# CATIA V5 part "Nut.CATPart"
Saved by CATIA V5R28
Part number: Nut
Bounding box of the stored display mesh (mm): x -6.998 to 6.998, y -6.998 to 6.998, z -4 to 15
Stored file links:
  C:\Users\Parisa\Desktop\tarah sanat\CAR JACK\Nut.CATPart
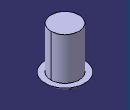
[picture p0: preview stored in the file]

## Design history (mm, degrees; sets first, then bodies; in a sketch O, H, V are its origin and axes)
Body1 (main body)
  Sketch1 on xy-plane, origin (0, 0, 0), H (1, 0, 0), V (0, 1, 0)
    circle A1 centre (0, 0) radius 5
    radius A1 = 5
  Pad1: profile Sketch1, direction (0, 0, 1), length 15
  Sketch2 on yz-plane, origin (0, 0, 0), H (0, 1, 0), V (0, 0, 1)
    spline S1 through (0, -4) (3.6404, -2.7278) (7, 0)
    line L1 (0, -4) -> (0, 0)
    point P1 (0, -4)
    line L2 (0, 0) -> (7, 0)
    point P2 (7, 0)
    point P3 (0, -4)
    point P4 (7, 0)
    length L2 = 7
    length L1 = 4
    coincidence: P3 P1, P4 P2
    vertical: L1 V
    horizontal: L2 H
  Shaft1: profile Sketch2, axis Sketch2.L1, angle 360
